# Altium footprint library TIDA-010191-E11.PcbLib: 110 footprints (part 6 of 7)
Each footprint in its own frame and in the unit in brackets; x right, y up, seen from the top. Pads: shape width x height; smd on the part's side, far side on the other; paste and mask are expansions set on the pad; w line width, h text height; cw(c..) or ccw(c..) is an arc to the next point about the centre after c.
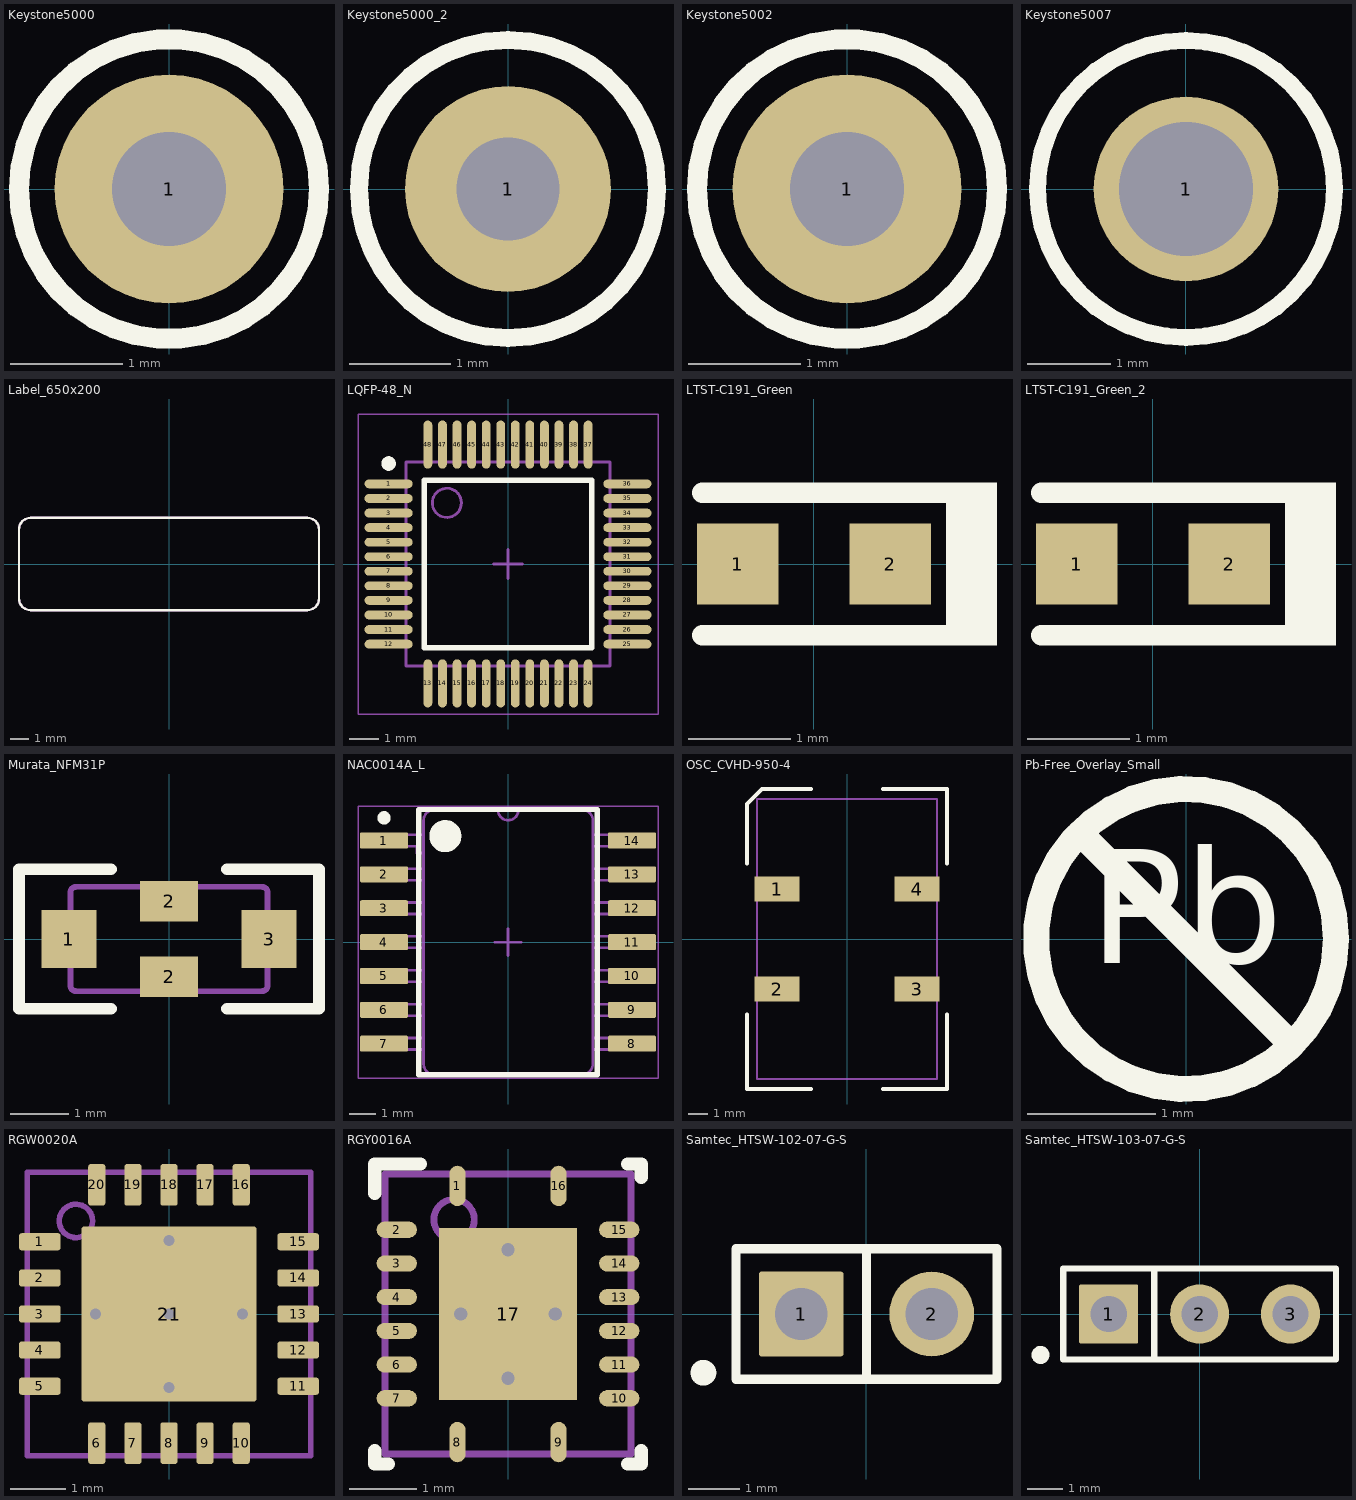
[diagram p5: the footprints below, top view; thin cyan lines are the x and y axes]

## Keystone5000 [mil] "For Keystone 500x miniature loop terminals"
height 181.1
pads (1):
  round 80 hole 40: 1(0,0)
Top Overlay:
  circle w7: c0,0 r52.5
Mechanical 5:
  circle w3.94: c0,0 r52.5
  text ".Designator" at -92.97,-15 h18
3D body "Keystone_5000.stp": height 181.97, standoff -118.11, extent -49,-49 49.04,49.24

## Keystone5000_2 [mil]
pads (1):
  round 80 hole 40: 1(0,0)
Top Overlay:
  circle w7: c0,0 r58
Mechanical 5:
  circle w5: c0,0 r58.31
  text ".Designator" at -98.8,85.02 h25
3D body "Keystone_5000.stp": height 181.97, standoff -118.11, extent -49,-49 49.04,49.24

## Keystone5002 [mil] "For Keystone 500x miniature loop terminals"
height 181.1
pads (1):
  round 80 hole 40: 1(0,0)
Top Overlay:
  circle w7: c0,0 r52.5
Mechanical 5:
  circle w3.94: c0,0 r52.5
  text ".Designator" at -92.97,-15 h18
3D body "Keystone_5002.stp": height 181.97, standoff -118.11, extent -49,-49 49.04,49.23

## Keystone5007 [mil] "Keystone Compact loops"
height 220
pads (1):
  round 87 hole 63: 1(0,0)
Top Overlay:
  circle w7.99: c0,0 r70
Mechanical 5:
  circle w5: c0,0 r70.71
  text ".Designator" at 64.7,-84.65 h25
3D body "Keystone_5007.stp": height 225.2, standoff -129.92, extent -63,-63 62.49,62.74

## Label_650x200 [mil] "Thermal Transfer Label"
height 1
pads (1):
  round 1 on Mech13: 0(0,0)
Top Overlay:
  lines w5: -325,-75 ccw(c-300,-75) -300,-100 300,-100 ccw(c300,-75) 325,-75 325,75 ccw(c300,75) 300,100 -300,100 ccw(c-300,75) -325,75 -325,-75
Mechanical 5:
  lines w5: -325,-75 ccw(c-300,-75) -300,-100 300,-100 ccw(c300,-75) 325,-75 325,75 ccw(c300,75) 300,100 -300,100 ccw(c-300,75) -325,75 -325,-75
  text ".Designator" at -60,-20 h40
3D body: height 1, standoff 0, extent -325.02,-100.02 325.02,100.02

## LQFP-48_N [mm] "QFP, 48-Leads, Body 7x7mm, Pitch 0.5mm, IPC Medium Density"
height 1.6
pads (48):
  oval 1.65x0.3 smd: 1(-4.1,2.75) 2(-4.1,2.25) 3(-4.1,1.75) 4(-4.1,1.25) 5(-4.1,0.75) 6(-4.1,0.25) 7(-4.1,-0.25) 8(-4.1,-0.75) 9(-4.1,-1.25) 10(-4.1,-1.75) 11(-4.1,-2.25) 12(-4.1,-2.75) 25(4.1,-2.75) 26(4.1,-2.25) 27(4.1,-1.75) 28(4.1,-1.25) 29(4.1,-0.75) 30(4.1,-0.25) 31(4.1,0.25) 32(4.1,0.75) 33(4.1,1.25) 34(4.1,1.75) 35(4.1,2.25) 36(4.1,2.75)
  oval 0.3x1.65 smd: 13(-2.75,-4.1) 14(-2.25,-4.1) 15(-1.75,-4.1) 16(-1.25,-4.1) 17(-0.75,-4.1) 18(-0.25,-4.1) 19(0.25,-4.1) 20(0.75,-4.1) 21(1.25,-4.1) 22(1.75,-4.1) 23(2.25,-4.1) 24(2.75,-4.1) 37(2.75,4.1) 38(2.25,4.1) 39(1.75,4.1) 40(1.25,4.1) 41(0.75,4.1) 42(0.25,4.1) 43(-0.25,4.1) 44(-0.75,4.1) 45(-1.25,4.1) 46(-1.75,4.1) 47(-2.25,4.1) 48(-2.75,4.1)
Top Overlay:
  circle w0.25: c-4.1,3.45 r0.125
  lines w0.2: -2.875,-2.875 -2.875,2.875 2.875,2.875 2.875,-2.875 -2.875,-2.875
Mechanical 5:
  circle w0.1: c-2.1,2.1 r0.5
  lines w0.1: -3.5,-3.5 3.5,-3.5 3.5,3.5 -3.5,3.5 -3.5,-3.5
Mechanical 15:
  lines w0.05: -5.15,-5.15 -5.15,5.15 5.15,5.15 5.15,-5.15 -5.15,-5.15
  lines w0.1: -0.5,0 0.5,0 ; 0,-0.5 0,0.5
3D body: height 1.6, standoff 0.05, extent -3.5,-3.5 3.5,3.5
3D body: height 1.61, standoff 0, extent -2.599,1.601 -1.6,2.6

## LTST-C191_Green [mm] "Lite-On"
height 0.65
pads (2):
  rect 0.8x0.8 smd: 1(-0.75,0) 2(0.75,0)
Top Overlay:
  region: 1.8,0.8 1.3,0.8 1.3,-0.8 1.8,-0.8
  lines w0.2: -1.1,-0.7 1.4,-0.7 ; -1.1,0.7 1.4,0.7
Mechanical 5:
  region: 1.8,0.75 1.3,0.75 1.3,-0.75 1.8,-0.75
  lines w0.1: -1.1,-0.7 1.4,-0.7 ; -1.1,0.7 1.4,0.7
  text ".Designator" at -1.225,-0.3 h0.64
3D body: height 0.65, standoff 0.2, extent -0.624,-0.449 0.624,0.449
3D body: height 0.2, standoff 0, extent -0.849,-0.449 0.849,0.449

## LTST-C191_Green_2 [mm]
pads (2):
  rect 0.8x0.8 smd: 1(-0.75,0) 2(0.75,0)
Top Overlay:
  region: 1.8,0.8 1.3,0.8 1.3,-0.8 1.8,-0.8
  lines w0.2: -1.1,-0.7 1.4,-0.7 ; -1.1,0.7 1.4,0.7
Mechanical 5:
  region: 1.8,0.75 1.3,0.75 1.3,-0.75 1.8,-0.75
  lines w0.1: -1.1,-0.7 1.4,-0.7 ; -1.1,0.7 1.4,0.7
  text ".Designator" at -0.462,-0.376 h0.64
3D body: height 0.2, standoff 0, extent -0.849,-0.449 0.849,0.449
3D body: height 0.65, standoff 0.2, extent -0.624,-0.449 0.624,0.449

## Murata_NFM31P [mm] "SMD, 3-Leads, Body 3.2x1.6mm"
height 1.5
pads (4):
  rect 0.95x1 smd paste-2 mask-2: 1(-1.725,0) 3(1.725,0)
  rect 1x0.7 smd paste-2 mask+0: 2(0,-0.65) 2(0,0.65)
Top Overlay:
  lines w0.2: -1,-1.2 -2.586,-1.2 -2.586,1.2 -1,1.2 ; 1,-1.2 2.586,-1.2 2.586,1.2 1,1.2
Top Paste:
  rectangle: -0.5,0.3 0.5,1.3
  region: 0.5,-0.3 -0.5,-0.3 -0.5,-1.3 0.5,-1.3
  rectangle: 1.25,-0.6 2.2,0.6
  region: -1.25,0.6 -2.2,0.6 -2.2,-0.6 -1.25,-0.6
Top Solder:
  region: -0.7,1 -2.2,1 -2.2,-1 -0.7,-1
  rectangle: 0.7,-1 2.2,1
Mechanical 5:
  lines w0.1: -1.7,-0.8 ccw(c-1.6,-0.8) -1.6,-0.9 1.6,-0.9 ccw(c1.6,-0.8) 1.7,-0.8 1.7,0.8 ccw(c1.6,0.8) 1.6,0.9 -1.6,0.9 ccw(c-1.6,0.8) -1.7,0.8 -1.7,-0.8
  text ".Designator" at -0.975,-0.3 h0.6
3D body "NFM31PC276B0J3L.stp": height 1.5, standoff 0, extent -1.7,-0.9 1.7,0.9

## NAC0014A_L [mm] "CFP-14"
height 2.13
pads (14):
  rrect17% 1.8x0.6 smd: 1(-4.65,3.81) 2(-4.65,2.54) 3(-4.65,1.27) 4(-4.65,0) 5(-4.65,-1.27) 6(-4.65,-2.54) 7(-4.65,-3.81) 8(4.65,-3.81) 9(4.65,-2.54) 10(4.65,-1.27) 11(4.65,0) 12(4.65,1.27) 13(4.65,2.54) 14(4.65,3.81)
Top Overlay:
  circle w0.6: c-2.35,3.975 r0.3
  circle w0.25: c-4.65,4.66 r0.125
  lines w0.2: -3.35,-4.975 -3.35,4.975 3.35,4.975 3.35,-4.975 -3.35,-4.975
Mechanical 5:
  drawing of 169 lines, arcs and shapes, not listed
  text ".Designator" at -0.475,1.9 h1.2
Mechanical 15:
  lines w0.05: -5.625,-5.1 -5.625,5.1 5.625,5.1 5.625,-5.1 -5.625,-5.1
  lines w0.1: -0.5,0 0.5,0 ; 0,-0.5 0,0.5
3D body "NAC0014A.stp": height 1.99, standoff 0.01, extent -5.207,-4.953 5.207,4.953

## OSC_CVHD-950-4 [mil] "Crystek recommended land pattern 2011-02-22 Rev H"
height 210
pads (4):
  rect 90x50 smd: 1(-140,100) 2(-140,-100) 3(140,-100) 4(140,100)
Top Overlay:
  lines w7.87: -200,-151.18 -200,-300 -71.73,-300 ; -200,151.18 -200,270 -170,300 -71.73,300 ; 71.73,-300 200,-300 200,-151.18 ; 71.73,300 200,300 200,151.18
Mechanical 5:
  lines w4: -180,-280 180,-280 180,280 -180,280 -180,-280
  text ".Designator" at -50,-20 h30
3D body "Crystek_CVHD-950.stp": height 209.06, standoff -0.39, extent -179.84,-279.53 180,279.53

## Pb-Free_Overlay_Small [mm]
height 1.66
Top Overlay:
  circle w0.203: c0,0 r1.168
  lines w0.203: -0.826,0.826 0.826,-0.826
  text "Pb" at -0.752,-0.48 h1.52

## RGW0020A [mm] "VQFN-20"
height 1
pads (21):
  rrect32% 0.75x0.31 smd: 1(-2.325,1.3) 2(-2.325,0.65) 3(-2.325,0) 4(-2.325,-0.65) 5(-2.325,-1.3) 11(2.325,-1.3) 12(2.325,-0.65) 13(2.325,0) 14(2.325,0.65) 15(2.325,1.3)
  rrect32% 0.31x0.75 smd: 6(-1.3,-2.325) 7(-0.65,-2.325) 8(0,-2.325) 9(0.65,-2.325) 10(1.3,-2.325) 16(1.3,2.325) 17(0.65,2.325) 18(0,2.325) 19(-0.65,2.325) 20(-1.3,2.325)
  rrect3% 3.15x3.15 smd paste-1.575: 21(0,0)
via 0,1.325 diameter 0.5 hole 0.2
via -1.325,0 diameter 0.5 hole 0.2
via 0,0 diameter 0.5 hole 0.2
via 1.325,0 diameter 0.5 hole 0.2
via 0,-1.325 diameter 0.5 hole 0.2
Top Paste:
  region: 0.1,0.15 0.1,1.42 0.1,1.43 0.108,1.448 0.122,1.462 0.14,1.47 0.15,1.47 1.42,1.47 1.43,1.47 1.448,1.462 1.462,1.448 1.47,1.43 1.47,1.42 1.47,0.15 1.47,0.14 1.462,0.122 1.448,0.108 1.43,0.1 1.42,0.1 0.15,0.1 0.14,0.1 0.122,0.108 0.108,0.122 0.1,0.14
  region: 0.1,-0.15 0.1,-1.42 0.1,-1.43 0.108,-1.448 0.122,-1.462 0.14,-1.47 0.15,-1.47 1.42,-1.47 1.43,-1.47 1.448,-1.462 1.462,-1.448 1.47,-1.43 1.47,-1.42 1.47,-0.15 1.47,-0.14 1.462,-0.122 1.448,-0.108 1.43,-0.1 1.42,-0.1 0.15,-0.1 0.14,-0.1 0.122,-0.108 0.108,-0.122 0.1,-0.14
  region: -0.1,-0.15 -0.1,-1.42 -0.1,-1.43 -0.108,-1.448 -0.122,-1.462 -0.14,-1.47 -0.15,-1.47 -1.42,-1.47 -1.43,-1.47 -1.448,-1.462 -1.462,-1.448 -1.47,-1.43 -1.47,-1.42 -1.47,-0.15 -1.47,-0.14 -1.462,-0.122 -1.448,-0.108 -1.43,-0.1 -1.42,-0.1 -0.15,-0.1 -0.14,-0.1 -0.122,-0.108 -0.108,-0.122 -0.1,-0.14
  region: -0.1,0.15 -0.1,1.42 -0.1,1.43 -0.108,1.448 -0.122,1.462 -0.14,1.47 -0.15,1.47 -1.42,1.47 -1.43,1.47 -1.448,1.462 -1.462,1.448 -1.47,1.43 -1.47,1.42 -1.47,0.15 -1.47,0.14 -1.462,0.122 -1.448,0.108 -1.43,0.1 -1.42,0.1 -0.15,0.1 -0.14,0.1 -0.122,0.108 -0.108,0.122 -0.1,0.14
Mechanical 5:
  circle w0.1: c-1.675,1.675 r0.3
  lines w0.1: -2.55,-2.55 2.55,-2.55 2.55,2.55 -2.55,2.55 -2.55,-2.55
  text ".Designator" at -1.854,-0.508 h1.02
3D body "RGW0020A.stp": height 1, standoff 0, extent -2.5,-2.5 2.5,2.5

## RGY0016A [mm] "QFN, 16-Leads, Body 4x3.5mm, Pitch 0.5mm, Thermal Pad 2.55x2.05mm, TI Recommended"
height 1
pads (17):
  oval 0.24x0.6 smd: 1(-0.75,1.9) 8(-0.75,-1.9) 9(0.75,-1.9) 16(0.75,1.9)
  oval 0.6x0.24 smd: 2(-1.65,1.25) 3(-1.65,0.75) 4(-1.65,0.25) 5(-1.65,-0.25) 6(-1.65,-0.75) 7(-1.65,-1.25) 10(1.65,-1.25) 11(1.65,-0.75) 12(1.65,-0.25) 13(1.65,0.25) 14(1.65,0.75) 15(1.65,1.25)
  rect 2.05x2.55 smd paste-1.025: 17(0,0)
via 0,-0.95 diameter 0.5 hole 0.2
via 0.7,0 diameter 0.5 hole 0.2
via -0.7,0 diameter 0.5 hole 0.2
via 0,0.95 diameter 0.5 hole 0.2
Top Overlay:
  lines w0.2: -1.975,-2.025 -1.975,-2.225 -1.775,-2.225 ; -1.975,1.79 -1.975,2.225 -1.3,2.225 ; 1.775,-2.225 1.975,-2.225 1.975,-2.025 ; 1.775,2.225 1.975,2.225 1.975,2.025
Top Paste:
  rectangle: 0.1,-1.24 1.017,-0.1
  region: -0.1,-0.1 -1.017,-0.1 -1.017,-1.24 -0.1,-1.24
  region: -0.1,1.24 -1.017,1.24 -1.017,0.1 -0.1,0.1
  rectangle: 0.1,0.1 1.017,1.24
Mechanical 5:
  circle w0.1: c-0.8,1.4 r0.3
  lines w0.1: -1.825,-2.075 -1.825,2.075 1.825,2.075 1.825,-2.075 -1.825,-2.075
  text ".Designator" at -1.397,-0.635 h0.76
3D body "RGY0016A.stp": height 1, standoff 0, extent -1.75,-2 1.75,2

## Samtec_HTSW-102-07-G-S [mm] "Samtec 100mil, 1x2, 230 mil above insulator"
height 8.382
pads (2):
  rrect6% 1.65x1.65 hole 1.016: 1(-1.27,0)
  round 1.65 hole 1.016: 2(1.27,0)
Top Overlay:
  circle w0.25: c-3.173,-1.143 r0.125
  lines w0.178: 0,-1.27 0,1.27 ; -2.54,-1.27 2.54,-1.27 2.54,1.27 -2.54,1.27 -2.54,-1.27
Mechanical 5:
  lines w0.127: -2.54,-1.27 -2.54,1.27 2.54,1.27 2.54,-1.27 -2.54,-1.27
  text ".Designator" at -1.524,-0.508 h0.86
3D body: height 2.54, standoff 0, extent -2.539,-1.269 2.539,1.269
3D body: height 8.38, standoff -2.03, extent -1.587,-0.317 -0.953,0.317
3D body: height 8.38, standoff -2.03, extent 0.953,-0.317 1.587,0.317

## Samtec_HTSW-103-07-G-S [mm] "Samtec 100mil, 1x3, 230 mil above insulator"
height 8.382
pads (3):
  rrect6% 1.65x1.65 hole 1.016: 1(-2.54,0)
  round 1.65 hole 1.016: 2(0,0) 3(2.54,0)
Top Overlay:
  circle w0.25: c-4.443,-1.143 r0.125
  lines w0.178: -1.27,-1.27 -1.27,1.27 ; -3.81,-1.27 -3.81,1.27 3.81,1.27 3.81,-1.27 -3.81,-1.27
Mechanical 5:
  rectangle: -3.048,-0.508 -2.032,0.508
  lines w0.127: -3.81,-1.27 3.81,-1.27 3.81,1.27 -3.81,1.27 -3.81,-1.27
  text ".Designator" at -1.016,-0.635 h1.02
3D body: height 2.54, standoff 0, extent -3.809,-1.269 3.809,1.269
3D body: height 8.38, standoff -2.03, extent 2.223,-0.317 2.857,0.317
3D body: height 8.38, standoff -2.03, extent -0.317,-0.317 0.317,0.317
3D body: height 8.38, standoff -2.03, extent -2.857,-0.317 -2.223,0.317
